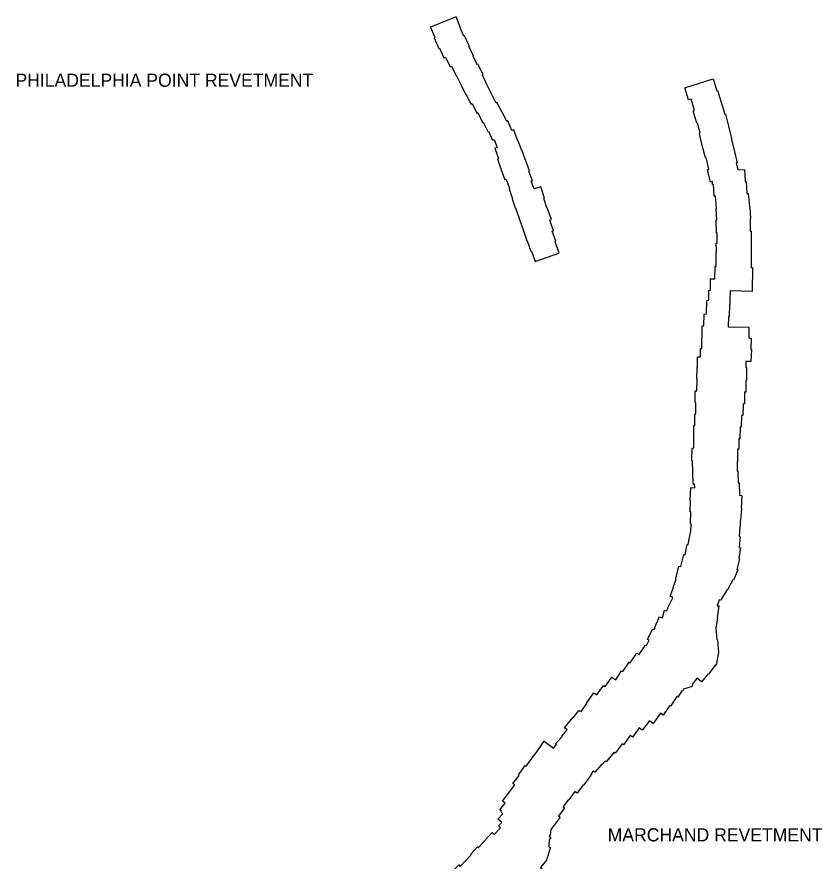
# Model space of a CAD drawing. Extents: x 2650582 to 3923188, y 277893 to 989177.
# Drawn here: x 3378629 to 3388432, y 595125 to 605400 of the extents above; entities that cross this region are included whole.
import ezdxf

# ---------------------------------------------------------------- set-up
doc = ezdxf.new("R2010")
doc.units = 0
doc.layers.add('Level 3', color=7, linetype='Continuous')

msp = doc.modelspace()

# ---------------------------------------------------------------- linework, layer by layer
at = {"layer": 'Level 3'}
for points in [[(3384607, 604133), (3384593, 604127), (3384536, 604244), (3384532, 604241), (3384477, 604358), (3384463, 604351), (3384409, 604462), (3384408, 604462), (3384351, 604576), (3384352, 604577), (3384297, 604691), (3384304, 604695), (3384244, 604820), (3384235, 604816), (3384182, 604924), (3384188, 604927), (3384132, 605045), (3384136, 605047), (3384077, 605171), (3384069, 605167), (3384026, 605266), (3384031, 605268), (3383979, 605400), (3383666, 605275), (3383717, 605148), (3383709, 605145), (3383766, 605016), (3383773, 605019), (3383829, 604901), (3383848, 604910), (3383904, 604792), (3383921, 604800), (3383979, 604682), (3383983, 604684), (3384035, 604576), (3384034, 604575), (3384093, 604452), (3384098, 604454), (3384156, 604338), (3384171, 604346), (3384229, 604228), (3384243, 604235), (3384299, 604116), (3384304, 604118), (3384361, 604003), (3384372, 604008)], [(3386762, 604538), (3387107, 604645), (3387151, 604501), (3387159, 604503), (3387203, 604360), (3387205, 604360), (3387248, 604216), (3387256, 604217), (3387293, 604069), (3387331, 603920), (3387325, 603918), (3387361, 603777), (3387362, 603777), (3387399, 603625), (3387385, 603622), (3387406, 603537)], [(3387097, 603396), (3387074, 603390), (3387036, 603540), (3387055, 603546), (3387021, 603686), (3387011, 603683), (3386973, 603835), (3386974, 603835), (3386938, 603982), (3386946, 603984), (3386915, 604108), (3386907, 604105), (3386861, 604255), (3386868, 604256), (3386880, 604260), (3386837, 604399), (3386807, 604390), (3386762, 604538)], [(3384925, 603306), (3384892, 603399), (3384905, 603403), (3384861, 603524), (3384871, 603528), (3384823, 603659), (3384820, 603658), (3384776, 603782), (3384771, 603780), (3384727, 603901), (3384723, 603899), (3384678, 604025), (3384656, 604017), (3384607, 604133)], [(3384372, 604008), (3384419, 603899), (3384439, 603908), (3384475, 603810), (3384448, 603801), (3384493, 603677), (3384480, 603673), (3384523, 603551), (3384520, 603550), (3384552, 603460), (3384568, 603418), (3384585, 603425), (3384627, 603310), (3384621, 603308), (3384664, 603186), (3384659, 603184), (3384693, 603087), (3384703, 603061), (3384704, 603062), (3384750, 602934), (3384748, 602933), (3384794, 602808), (3384792, 602807), (3384839, 602675), (3384841, 602676), (3384887, 602547), (3384894, 602550), (3384941, 602421), (3385158, 602500), (3385158, 602500)], [(3387406, 603537), (3387487, 603543), (3387494, 603395), (3387508, 603396), (3387517, 603251), (3387533, 603251), (3387549, 603088), (3387554, 603088), (3387560, 602948), (3387555, 602946), (3387557, 602790), (3387567, 602790), (3387569, 602609), (3387570, 602452), (3387568, 602351), (3387584, 602351), (3387579, 602058), (3387313, 602065), (3387309, 601953), (3387308, 601903), (3387305, 601903), (3387301, 601755), (3387292, 601753), (3387290, 601629), (3387542, 601623), (3387539, 601492), (3387569, 601489), (3387563, 601351), (3387572, 601351), (3387564, 601204), (3387503, 601204)], [(3386952, 601264), (3386953, 601363), (3386966, 601365), (3386971, 601638), (3386994, 601638), (3386996, 601782), (3387026, 601784), (3387029, 601948), (3387053, 601951), (3387055, 602070), (3387072, 602072), (3387074, 602213), (3387127, 602213), (3387130, 602361), (3387143, 602361), (3387142, 602546), (3387146, 602547), (3387143, 602647), (3387156, 602647), (3387154, 602770), (3387148, 602769), (3387142, 602929), (3387150, 602929), (3387142, 603068), (3387147, 603070), (3387134, 603217), (3387119, 603217), (3387111, 603360), (3387099, 603358), (3387097, 603396)], [(3385158, 602500), (3385233, 602526), (3385184, 602667), (3385192, 602670), (3385147, 602791), (3385163, 602797), (3385116, 602927), (3385138, 602935), (3385087, 603076), (3385082, 603074), (3385043, 603190), (3385053, 603193), (3385007, 603333), (3384925, 603306)], [(3386869, 600154), (3386872, 600425), (3386881, 600426), (3386882, 600566), (3386894, 600567), (3386895, 600708), (3386888, 600709), (3386888, 600849), (3386909, 600848), (3386912, 600991), (3386907, 600992), (3386910, 601132), (3386915, 601133), (3386917, 601264), (3386952, 601264)], [(3387503, 601204), (3387505, 601133), (3387510, 601133), (3387511, 600977), (3387502, 600975), (3387503, 600834), (3387487, 600834), (3387486, 600691), (3387470, 600690), (3387468, 600550), (3387452, 600549), (3387447, 600409), (3387434, 600407), (3387431, 600268), (3387419, 600268), (3387417, 600138)], [(3386583, 598348), (3386622, 598454), (3386617, 598456), (3386655, 598561), (3386652, 598562), (3386690, 598715), (3386711, 598710), (3386747, 598856), (3386760, 598853), (3386760, 598854), (3386766, 598853), (3386790, 598979), (3386801, 598977), (3386830, 599129), (3386833, 599128), (3386839, 599232), (3386828, 599232), (3386833, 599377), (3386825, 599377), (3386829, 599515), (3386827, 599515), (3386833, 599672), (3386881, 599670), (3386880, 599711), (3386861, 599712), (3386860, 599853), (3386857, 599853), (3386856, 599996), (3386845, 599996), (3386850, 600152), (3386869, 600154)], [(3387417, 600138), (3387403, 600138), (3387404, 599994), (3387398, 599994), (3387398, 599869), (3387407, 599869), (3387410, 599729), (3387424, 599729), (3387425, 599577), (3387454, 599575), (3387448, 599421), (3387451, 599421), (3387440, 599269), (3387436, 599269)], [(3387436, 599269), (3387434, 599200), (3387431, 599200), (3387424, 599074), (3387436, 599073), (3387421, 598942), (3387440, 598939), (3387419, 598807), (3387426, 598805), (3387396, 598676), (3387406, 598671), (3387352, 598545), (3387345, 598547), (3387281, 598427), (3387276, 598430), (3387208, 598316), (3387207, 598316)], [(3385164, 596498), (3385200, 596543), (3385187, 596553), (3385268, 596643), (3385263, 596646), (3385330, 596722), (3385297, 596749), (3385396, 596873), (3385403, 596867), (3385471, 596960), (3385497, 596944), (3385569, 597043), (3385563, 597049), (3385653, 597174), (3385689, 597150), (3385772, 597264), (3385791, 597251), (3385873, 597365), (3385921, 597333), (3385992, 597440), (3386006, 597432), (3386084, 597548), (3386097, 597540), (3386178, 597657), (3386204, 597640), (3386283, 597754), (3386293, 597749), (3386328, 597814), (3386308, 597823), (3386368, 597950), (3386386, 597942), (3386421, 598029), (3386425, 598028), (3386447, 598098), (3386489, 598086), (3386513, 598178), (3386539, 598171), (3386557, 598206), (3386555, 598207), (3386609, 598323), (3386607, 598324), (3386613, 598336), (3386583, 598348)], [(3387207, 598316), (3387202, 598299), (3387179, 598306), (3387156, 598233), (3387175, 598230), (3387154, 598084), (3387158, 598083), (3387140, 597965), (3387151, 597819), (3387159, 597820), (3387170, 597663), (3387172, 597663), (3387142, 597511), (3387135, 597512), (3387048, 597402), (3387044, 597404), (3386963, 597309), (3386911, 597351), (3386851, 597277), (3386857, 597269), (3386847, 597260), (3386850, 597251), (3386746, 597216)], [(3386746, 597216), (3386731, 597193), (3386725, 597197), (3386675, 597120), (3386663, 597128), (3386585, 597010), (3386575, 597016), (3386498, 596902), (3386466, 596925), (3386374, 596798), (3386330, 596832), (3386242, 596719), (3386204, 596748), (3386123, 596633), (3386096, 596652), (3386016, 596539), (3385999, 596551), (3385913, 596438), (3385900, 596450), (3385805, 596333), (3385793, 596343), (3385760, 596305), (3385754, 596310), (3385665, 596209), (3385648, 596224), (3385619, 596190), (3385626, 596184), (3385609, 596164), (3385613, 596161)], [(3384532, 595594), (3384486, 595637), (3384547, 595702), (3384522, 595726), (3384529, 595734), (3384508, 595751), (3384573, 595830), (3384543, 595853), (3384690, 596052), (3384667, 596069), (3384743, 596169), (3384736, 596175), (3384819, 596288), (3384830, 596280), (3384968, 596467), (3384966, 596469), (3385050, 596583), (3385164, 596498)], [(3385613, 596161), (3385529, 596048), (3385524, 596052), (3385449, 595952), (3385423, 595972), (3385348, 595871), (3385344, 595874), (3385278, 595786), (3385297, 595772), (3385223, 595673), (3385243, 595658), (3385160, 595546), (3385158, 595547), (3385130, 595510), (3385120, 595435), (3385110, 595436), (3385110, 595430), (3385131, 595413), (3385108, 595385)], [(3384200, 594680), (3383947, 594951), (3383953, 594956), (3383919, 594992), (3384008, 595078), (3384024, 595061), (3384088, 595125), (3384087, 595126), (3384160, 595202), (3384154, 595208), (3384239, 595299), (3384248, 595290), (3384314, 595360), (3384312, 595361), (3384416, 595473), (3384440, 595450), (3384519, 595529), (3384494, 595553), (3384532, 595594)], [(3385108, 595385), (3385106, 595298), (3385125, 595292), (3385077, 595140), (3385072, 595141), (3385076, 595137), (3385004, 595047), (3385023, 595031), (3384935, 594931), (3384952, 594916), (3384839, 594790), (3384845, 594784), (3384777, 594715), (3384782, 594708), (3384669, 594598), (3384656, 594612), (3384553, 594510), (3384521, 594543), (3384423, 594450), (3384390, 594483)]]:
    msp.add_lwpolyline(points, dxfattribs=at)

# ---------------------------------------------------------------- texts
for s, p in [('PHILADELPHIA POINT REVETMENT', (3378612, 604549)), ('MARCHAND REVETMENT', (3385822, 595365))]:
    msp.add_text(s, height=160, dxfattribs=at).set_placement(p)

doc.saveas('drawing.dxf')
